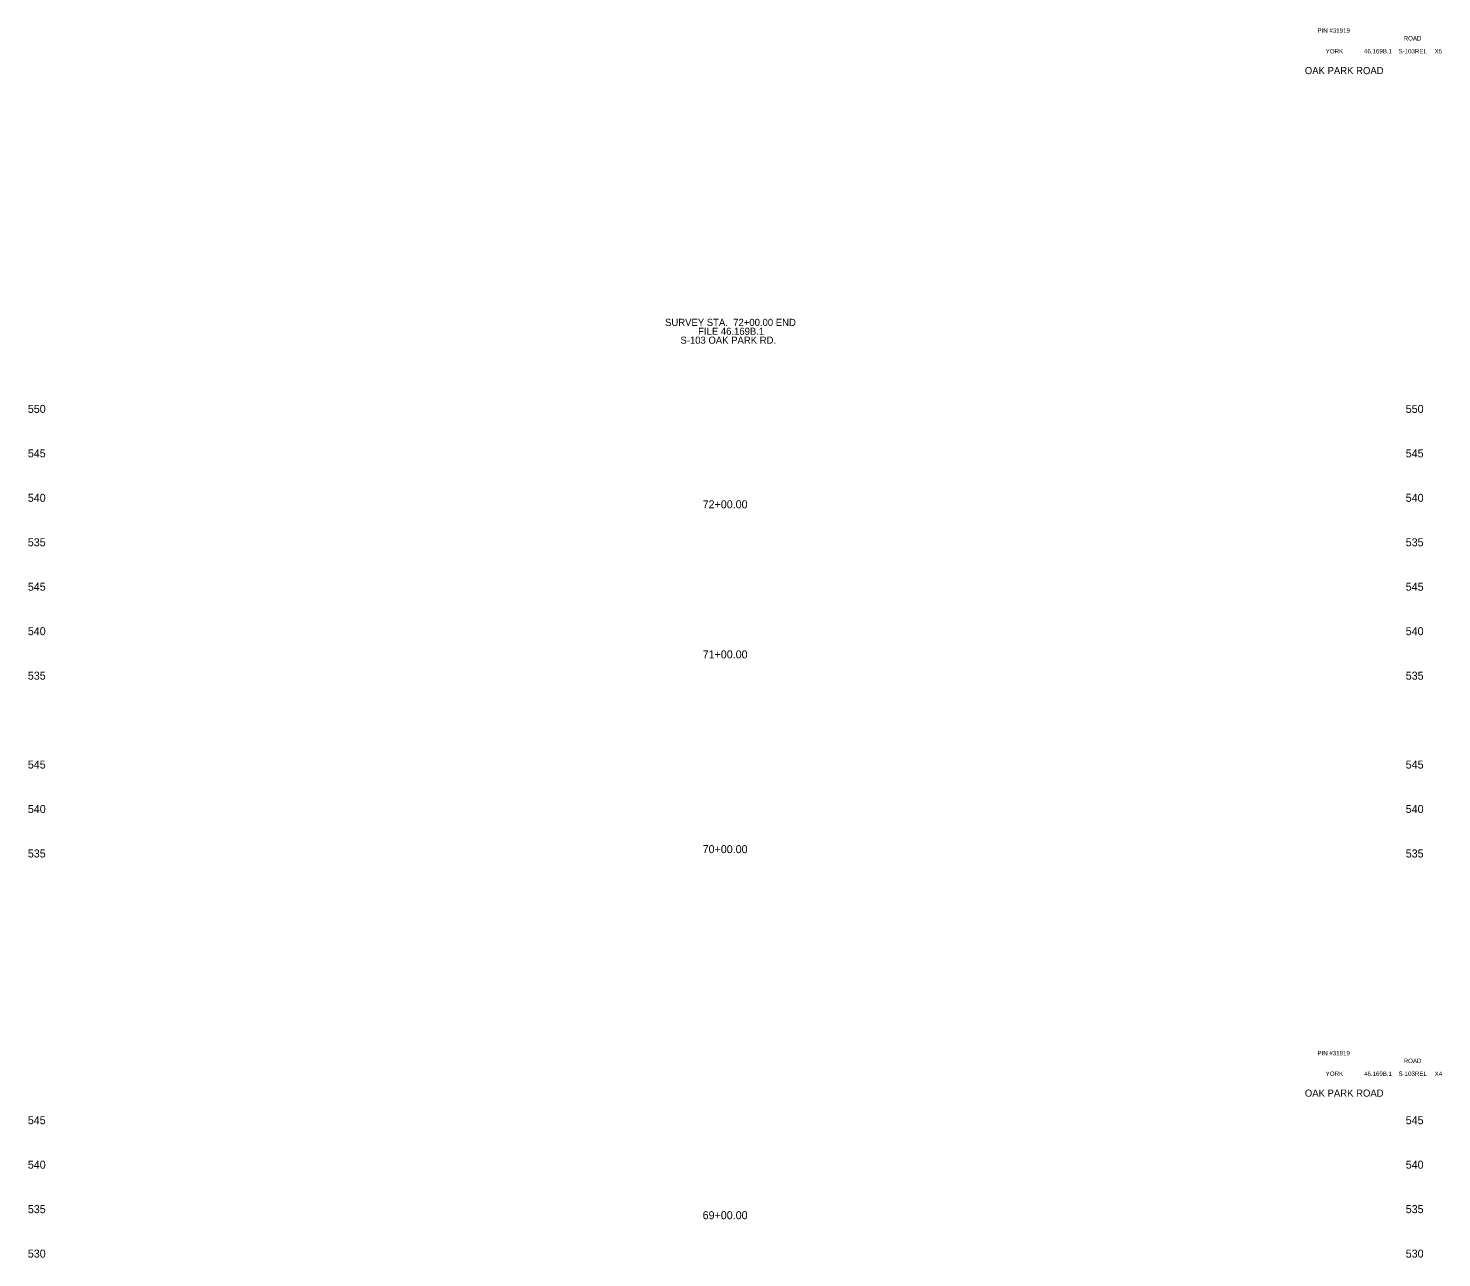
# Model space of a CAD drawing. Extents: x 1001 to 1160, y 1003 to 1563.
# Drawn here: x 1001.5 to 1160.5, y 1425 to 1563.3 of the extents above; entities that cross this region are included whole.
import ezdxf

# ---------------------------------------------------------------- set-up
doc = ezdxf.new("R2010")
doc.units = 0
for name, color, linetype in [('Level 25', 7, 'Continuous'), ('Level 41', 7, 'Continuous'), ('Level 56', 7, 'Continuous')]:
    doc.layers.add(name, color=color, linetype=linetype)

msp = doc.modelspace()

# ---------------------------------------------------------------- texts
at = {"layer": 'Level 25'}
for s, p in [('72+00.00', (1077.36, 1509.27)), ('71+00.00', (1077.36, 1492.39)), ('70+00.00', (1077.36, 1470.49)), ('69+00.00', (1077.36, 1429.32))]:
    msp.add_text(s, height=0.9, dxfattribs=at).set_placement(p)
at = {"layer": 'Level 41'}
for s, height, p in [('PIN #31919', 0.5, (1146.52, 1562.75)), ('ROAD', 0.5, (1156.22, 1561.88)), ('YORK', 0.5, (1147.45, 1560.43)), ('46.169B.1', 0.5, (1151.76, 1560.43)), ('S-103REL', 0.5, (1155.64, 1560.43)), ('X5', 0.5, (1159.7, 1560.43)), ('OAK PARK ROAD', 0.8, (1145.1, 1558.1)), ('SURVEY STA.  72+00.00 END', 0.8, (1073.13, 1529.78)), ('FILE 46.169B.1', 0.8, (1076.85, 1528.78)), ('S-103 OAK PARK RD.', 0.8, (1074.86, 1527.78)), ('PIN #31919', 0.5, (1146.52, 1447.75)), ('ROAD', 0.5, (1156.22, 1446.88)), ('YORK', 0.5, (1147.45, 1445.43)), ('46.169B.1', 0.5, (1151.76, 1445.43)), ('S-103REL', 0.5, (1155.64, 1445.43)), ('X4', 0.5, (1159.7, 1445.43)), ('OAK PARK ROAD', 0.8, (1145.1, 1443.1))]:
    msp.add_text(s, height=height, dxfattribs=at).set_placement(p)
at = {"layer": 'Level 56'}
for s, p in [('550', (1001.45, 1520)), ('550', (1156.45, 1520)), ('545', (1001.45, 1515)), ('545', (1156.45, 1515)), ('540', (1001.45, 1510)), ('540', (1156.45, 1510)), ('535', (1001.45, 1505)), ('535', (1156.45, 1505)), ('545', (1001.45, 1500)), ('545', (1156.45, 1500)), ('540', (1001.45, 1495)), ('540', (1156.45, 1495)), ('535', (1001.45, 1490)), ('535', (1156.45, 1490)), ('545', (1001.45, 1480)), ('545', (1156.45, 1480)), ('540', (1001.45, 1475)), ('540', (1156.45, 1475)), ('535', (1001.45, 1470)), ('535', (1156.45, 1470)), ('545', (1001.45, 1440)), ('545', (1156.45, 1440)), ('540', (1001.45, 1435)), ('540', (1156.45, 1435)), ('535', (1001.45, 1430)), ('535', (1156.45, 1430)), ('530', (1001.45, 1425)), ('530', (1156.45, 1425))]:
    msp.add_text(s, height=0.9, dxfattribs=at).set_placement(p)

doc.saveas('drawing.dxf')
